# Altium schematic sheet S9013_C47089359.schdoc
size 127 x 101 mm
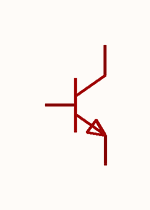
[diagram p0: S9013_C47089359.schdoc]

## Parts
Q?  s9013_c47089359  [SOT-23-3_L2.9-W1.3-P1.90-LS2.4-BR]  (value not drawn)

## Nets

Not connected (* = marked no-connect by the designer): Q? 1(B) 2(E) 3(C)

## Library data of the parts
Q? = s9013_c47089359: 晶体管类型:NPN;集电极电流(Ic):500mA;集射极击穿电压(Vceo):25V;耗散功率(Pd):300mW;直流电流增益(hFE):400;; Manufacturer: CJ(江苏长电/长晶); ManufacturerPart: S9013; AddInBom: yes; ModelId: c62791f0466c4ae2a892c056b845b0ca; ModelName: SOT-23-3P_L2.9-W1.3-H1.0-LS2.4-P0.95; ModelTransform: 98.425,114.173,0,180,0,0,0.0005,-0.0005,0; type: NPN; Current - Collector(Ic): 500mA; Collector - Emitter Voltage VCEO: 25V; Pd - Power Dissipation: 300mW; DC Current Gain: 400; Transition frequency(fT): 150MHz; Current - Collector Cutoff: 100nA; Vce Saturation(VCE(sat)): 600mV; Emitter-Base Voltage(Vebo): 5V; Number: 1个NPN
